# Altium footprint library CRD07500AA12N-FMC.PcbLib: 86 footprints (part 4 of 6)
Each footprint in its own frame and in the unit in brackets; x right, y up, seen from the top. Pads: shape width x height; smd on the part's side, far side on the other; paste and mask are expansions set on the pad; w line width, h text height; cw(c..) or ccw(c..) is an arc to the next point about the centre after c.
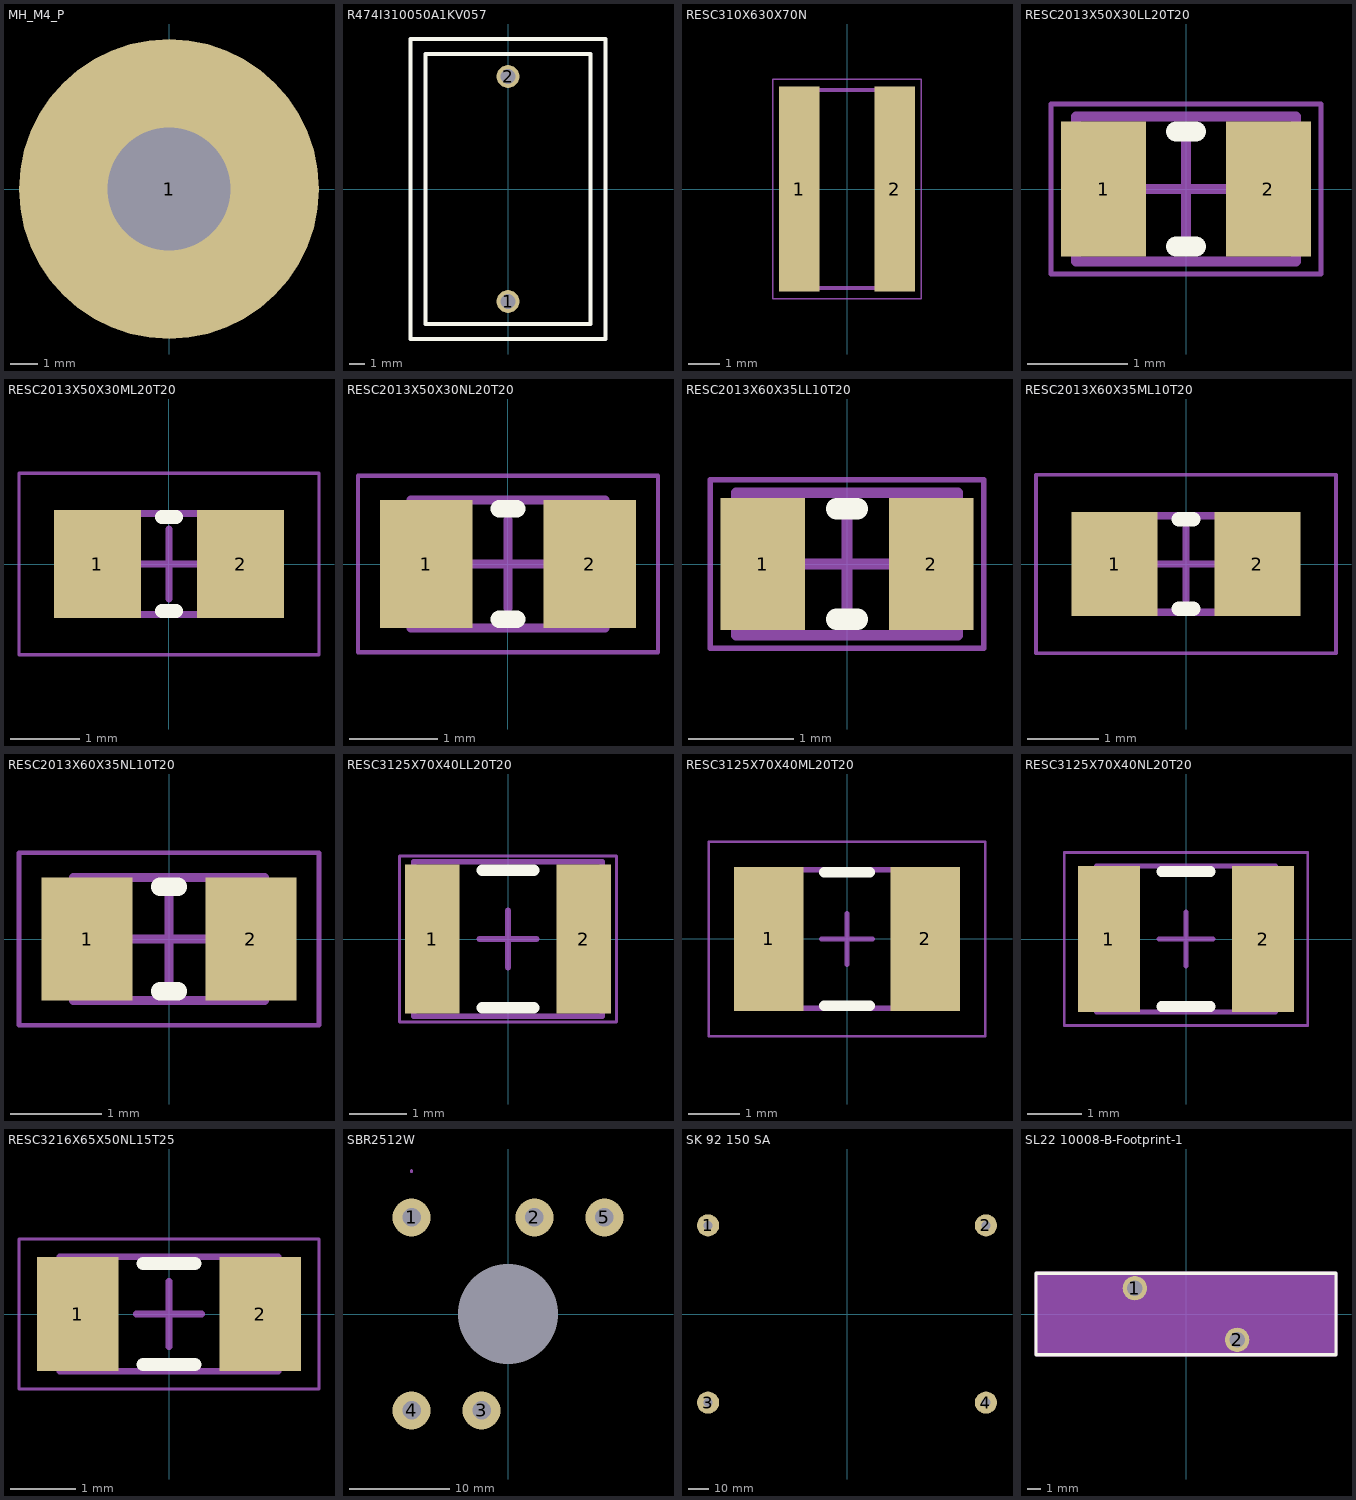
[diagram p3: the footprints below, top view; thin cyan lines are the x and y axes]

## MH_M4_P [mm] "M4 plated mounting hole"
pads (1):
  round 11 hole 4.5: 1(0,0)
3D body "Extended Standoff (102mm).STEP": height 102.05, standoff 0.05, extent -4,-4.619 4,4.619

## R474I310050A1KV057 [mm] "0.1uF 1KVDC X1"
pads (2):
  round 1.524 hole 1: 1(0,-7.5) 2(0,7.5)
Top Overlay:
  lines w0.254: -6.5,-10 6.5,-10 6.5,10 -6.5,10 -6.5,-10 ; -5.5,-9 5.5,-9 5.5,9 -5.5,9 -5.5,-9
3D body "User Library-FILM_BLUE_P1500L1800W1100H1900PD80 (bypass cap).STEP": height 19, standoff -5, extent -5.5,-9 5.5,9

## RESC310X630X70N [mm]
pads (2):
  rect 1.29x6.52 smd: 1(-1.515,0) 2(1.515,0)
Mechanical 13:
  lines w0.127: -1.55,-3.15 -1.55,3.15 1.55,3.15 1.55,-3.15 -1.55,-3.15
Mechanical 15:
  lines w0.05: -2.36,-3.5 -2.36,3.5 2.36,3.5 2.36,-3.5 -2.36,-3.5
3D body "Wide 2512.stp": height 0.7, standoff 0, extent -1.6,-3.15 1.6,3.15

## RESC2013X50X30LL20T20 [mm] "Chip Resistor, 2-Leads, Body 2.00x1.25mm, IPC High Density"
height 0.5
pads (2):
  rect 0.85x1.35 smd: 1(-0.825,0) 2(0.825,0)
Top Overlay:
  lines w0.2: -0.1,-0.575 0.1,-0.575 ; -0.1,0.575 0.1,0.575
Mechanical 13:
  lines w0.1: -1.1,-0.725 1.1,-0.725 1.1,0.725 -1.1,0.725 -1.1,-0.725
Mechanical 15:
  lines w0.05: -1.35,-0.85 1.35,-0.85 1.35,0.85 -1.35,0.85 -1.35,-0.85
  lines w0.1: -0.5,0 0.5,0 ; 0,-0.5 0,0.5
3D body: height 0.5, standoff 0, extent 0.8,-0.725 1.1,0.725
3D body: height 0.5, standoff 0, extent -1.1,-0.725 -0.8,0.725
3D body: height 0.5, standoff 0, extent -0.8,-0.725 0.8,0.725

## RESC2013X50X30ML20T20 [mm] "Chip Resistor, 2-Leads, Body 2.00x1.25mm, IPC Low Density"
height 0.5
pads (2):
  rect 1.25x1.55 smd: 1(-1.025,0) 2(1.025,0)
Top Overlay:
  lines w0.2: -0.1,-0.675 0.1,-0.675 ; -0.1,0.675 0.1,0.675
Mechanical 13:
  lines w0.1: -1.1,-0.725 -1.1,0.725 1.1,0.725 1.1,-0.725 -1.1,-0.725
Mechanical 15:
  lines w0.05: -2.15,-1.3 -2.15,1.3 2.15,1.3 2.15,-1.3 -2.15,-1.3
  lines w0.1: -0.5,0 0.5,0 ; 0,-0.5 0,0.5
3D body: height 0.5, standoff 0, extent -0.8,-0.725 0.8,0.725
3D body: height 0.5, standoff 0, extent -1.1,-0.725 -0.8,0.725
3D body: height 0.5, standoff 0, extent 0.8,-0.725 1.1,0.725

## RESC2013X50X30NL20T20 [mm] "Chip Resistor, 2-Leads, Body 2.00x1.25mm, IPC Medium Density"
height 0.5
pads (2):
  rect 1.05x1.45 smd: 1(-0.925,0) 2(0.925,0)
Top Overlay:
  lines w0.2: -0.1,-0.625 0.1,-0.625 ; -0.1,0.625 0.1,0.625
Mechanical 13:
  lines w0.1: -1.1,-0.725 -1.1,0.725 1.1,0.725 1.1,-0.725 -1.1,-0.725
Mechanical 15:
  lines w0.05: -1.7,-1 -1.7,1 1.7,1 1.7,-1 -1.7,-1
  lines w0.1: -0.5,0 0.5,0 ; 0,-0.5 0,0.5
3D body: height 0.5, standoff 0, extent -0.8,-0.725 0.8,0.725
3D body: height 0.5, standoff 0, extent -1.1,-0.725 -0.8,0.725
3D body: height 0.5, standoff 0, extent 0.8,-0.725 1.1,0.725

## RESC2013X60X35LL10T20 [mm] "Chip Resistor, 2-Leads, Body 2.00x1.25mm, IPC High Density"
height 0.6
pads (2):
  rect 0.8x1.25 smd: 1(-0.8,0) 2(0.8,0)
Top Overlay:
  lines w0.2: -0.1,-0.525 0.1,-0.525 ; -0.1,0.525 0.1,0.525
Mechanical 13:
  lines w0.1: -1.05,-0.675 1.05,-0.675 1.05,0.675 -1.05,0.675 -1.05,-0.675
Mechanical 15:
  lines w0.05: -1.3,-0.8 1.3,-0.8 1.3,0.8 -1.3,0.8 -1.3,-0.8
  lines w0.1: -0.5,0 0.5,0 ; 0,-0.5 0,0.5
3D body: height 0.6, standoff 0, extent 0.7,-0.675 1.05,0.675
3D body: height 0.6, standoff 0, extent -1.05,-0.675 -0.7,0.675
3D body: height 0.6, standoff 0, extent -0.7,-0.675 0.7,0.675

## RESC2013X60X35ML10T20 [mm] "Chip Resistor, 2-Leads, Body 2.00x1.25mm, IPC Low Density"
height 0.6
pads (2):
  rect 1.2x1.45 smd: 1(-1,0) 2(1,0)
Top Overlay:
  lines w0.2: -0.1,-0.625 0.1,-0.625 ; -0.1,0.625 0.1,0.625
Mechanical 13:
  lines w0.1: -1.05,-0.675 1.05,-0.675 1.05,0.675 -1.05,0.675 -1.05,-0.675
Mechanical 15:
  lines w0.05: -2.1,-1.25 2.1,-1.25 2.1,1.25 -2.1,1.25 -2.1,-1.25
  lines w0.1: -0.5,0 0.5,0 ; 0,-0.5 0,0.5
3D body: height 0.6, standoff 0, extent 0.7,-0.675 1.05,0.675
3D body: height 0.6, standoff 0, extent -1.05,-0.675 -0.7,0.675
3D body: height 0.6, standoff 0, extent -0.7,-0.675 0.7,0.675

## RESC2013X60X35NL10T20 [mm] "Chip Resistor, 2-Leads, Body 2.00x1.25mm, IPC Medium Density"
height 0.6
pads (2):
  rect 1x1.35 smd: 1(-0.9,0) 2(0.9,0)
Top Overlay:
  lines w0.2: -0.1,-0.575 0.1,-0.575 ; -0.1,0.575 0.1,0.575
Mechanical 13:
  lines w0.1: -1.05,-0.675 -1.05,0.675 1.05,0.675 1.05,-0.675 -1.05,-0.675
Mechanical 15:
  lines w0.05: -1.65,-0.95 -1.65,0.95 1.65,0.95 1.65,-0.95 -1.65,-0.95
  lines w0.1: -0.5,0 0.5,0 ; 0,-0.5 0,0.5
3D body: height 0.6, standoff 0, extent -0.7,-0.675 0.7,0.675
3D body: height 0.6, standoff 0, extent -1.05,-0.675 -0.7,0.675
3D body: height 0.6, standoff 0, extent 0.7,-0.675 1.05,0.675

## RESC3125X70X40LL20T20 [mm] "Chip Resistor, 2-Leads, Body 3.10x2.50mm, IPC High Density"
height 0.7
pads (2):
  rect 0.95x2.6 smd: 1(-1.325,0) 2(1.325,0)
Top Overlay:
  lines w0.2: -0.45,-1.2 0.45,-1.2 ; -0.45,1.2 0.45,1.2
Mechanical 13:
  lines w0.1: -1.65,-1.35 1.65,-1.35 1.65,1.35 -1.65,1.35 -1.65,-1.35
Mechanical 15:
  lines w0.05: -1.9,-1.45 1.9,-1.45 1.9,1.45 -1.9,1.45 -1.9,-1.45
  lines w0.1: -0.5,0 0.5,0 ; 0,-0.5 0,0.5
3D body: height 0.7, standoff 0, extent 1.25,-1.35 1.65,1.35
3D body: height 0.7, standoff 0, extent -1.65,-1.35 -1.25,1.35
3D body: height 0.7, standoff 0, extent -1.25,-1.35 1.25,1.35

## RESC3125X70X40ML20T20 [mm] "Chip Resistor, 2-Leads, Body 3.10x2.50mm, IPC Low Density"
height 0.7
pads (2):
  rect 1.35x2.8 smd: 1(-1.525,0) 2(1.525,0)
Top Overlay:
  lines w0.2: -0.45,-1.3 0.45,-1.3 ; -0.45,1.3 0.45,1.3
Mechanical 13:
  lines w0.1: -1.65,-1.35 -1.65,1.35 1.65,1.35 1.65,-1.35 -1.65,-1.35
Mechanical 15:
  lines w0.05: -2.7,-1.9 -2.7,1.9 2.7,1.9 2.7,-1.9 -2.7,-1.9
  lines w0.1: -0.5,0 0.5,0 ; 0,-0.5 0,0.5
3D body: height 0.7, standoff 0, extent -1.25,-1.35 1.25,1.35
3D body: height 0.7, standoff 0, extent -1.65,-1.35 -1.25,1.35
3D body: height 0.7, standoff 0, extent 1.25,-1.35 1.65,1.35

## RESC3125X70X40NL20T20 [mm] "Chip Resistor, 2-Leads, Body 3.10x2.50mm, IPC Medium Density"
height 0.7
pads (2):
  rect 1.15x2.7 smd: 1(-1.425,0) 2(1.425,0)
Top Overlay:
  lines w0.2: -0.45,-1.25 0.45,-1.25 ; -0.45,1.25 0.45,1.25
Mechanical 13:
  lines w0.1: -1.65,-1.35 1.65,-1.35 1.65,1.35 -1.65,1.35 -1.65,-1.35
Mechanical 15:
  lines w0.05: -2.25,-1.6 2.25,-1.6 2.25,1.6 -2.25,1.6 -2.25,-1.6
  lines w0.1: -0.5,0 0.5,0 ; 0,-0.5 0,0.5
3D body: height 0.7, standoff 0, extent 1.25,-1.35 1.65,1.35
3D body: height 0.7, standoff 0, extent -1.65,-1.35 -1.25,1.35
3D body: height 0.7, standoff 0, extent -1.25,-1.35 1.25,1.35

## RESC3216X65X50NL15T25 [mm] "Chip Resistor, 2-Leads, Body 3.20x1.60mm, IPC Medium Density"
height 0.65
pads (2):
  rect 1.25x1.75 smd: 1(-1.4,0) 2(1.4,0)
Top Overlay:
  lines w0.2: -0.4,-0.775 0.4,-0.775 ; -0.4,0.775 0.4,0.775
Mechanical 13:
  lines w0.1: -1.675,-0.875 1.675,-0.875 1.675,0.875 -1.675,0.875 -1.675,-0.875
Mechanical 15:
  lines w0.05: -2.3,-1.15 2.3,-1.15 2.3,1.15 -2.3,1.15 -2.3,-1.15
  lines w0.1: -0.5,0 0.5,0 ; 0,-0.5 0,0.5
3D body: height 0.65, standoff 0, extent 1.175,-0.875 1.675,0.875
3D body: height 0.65, standoff 0, extent -1.675,-0.875 -1.175,0.875
3D body: height 0.65, standoff 0, extent -1.175,-0.875 1.175,0.875

## SBR2512W [mm] "3P diode bridge 1200V 25A"
pads (6):
  round 3.81 hole 1.85: 1(-9.65,9.65) 2(2.649,9.65) 3(-2.649,-9.65) 4(-9.65,-9.65) 5(9.65,9.65)
  round 0 hole 10 unplated: 6(0,0)
Bottom Overlay:
  lines w0.254: -14.4,-9.65 -14.4,-14.4 ; -14.4,9.65 -14.4,14.4 ; -14.351,-9.652 -11.938,-9.652 ; -14.351,9.652 -11.938,9.652 ; -9.652,-14.351 -9.652,-11.938 ; -9.652,11.938 -9.652,14.351 ; -9.65,-14.4 -14.4,-14.4 ; -9.65,14.4 -14.4,14.4 ; -14.4,-14.4 -14.4,14.4 ; -14.4,-14.4 14.4,-14.4 14.4,14.4 -14.4,14.4 ; -15,-15 -15,15 15,15 15,-15 -15,-15
Mechanical 1:
  lines w0.254: -9.652,14.224 -9.652,14.351
3D body "Diode Bridge + Bolt.STEP": height 0, standoff -19, extent -14.266,-14.234 14.234,14.266

## SK 92 150 SA [mm]
pads (4):
  round 11 hole 4.5: 1(-69,44) 2(69,44) 3(-69,-44) 4(69,-44)
3D body "Fischer Elektronik SK 85100 SA + Standoffs.STEP": height 52.09, standoff 0.09, extent -75.011,-50.029 74.989,49.97

## SL22 10008-B-Footprint-1 [mil]
pads (2):
  round 70 hole 45: 1(-147.64,74.41) 2(147.64,-74.41)
Top Overlay:
  lines w10: -433.07,-118.11 -433.07,118.11 433.07,118.11 433.07,-118.11 -433.07,-118.11
Top Component Outline:
  region: -433.07,-118.11 -433.07,118.11 433.07,118.11 433.07,-118.11
Top Assembly:
  lines w10: -433.07,-118.11 433.07,-118.11 433.07,118.11 -433.07,118.11 -433.07,-118.11
3D body "SL22 10008-B.STEP": height 1023.62, standoff -295.28, extent -433.07,-118.1 433.08,118.12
